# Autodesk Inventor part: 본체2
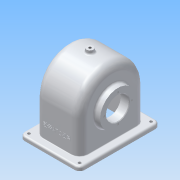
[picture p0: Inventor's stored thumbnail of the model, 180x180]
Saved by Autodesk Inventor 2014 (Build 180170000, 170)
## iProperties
Created: 2016-01
Part Number: 본체2
Material: 알루미늄 6061
Document SubType Name: Modeling
Designer: User
Mass: 794.903 g
Surface Area: 1006.9 cm^2
Volume: 293.322 cm^3
Density: 2.71 g/cm^3
Appearance: 알루미늄 - 평지
Author: User
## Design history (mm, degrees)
sketch "스케치1"
  geometry: L1 (-57, 0)-(57, 0); L2 (57, 0)-(57, -64); L3 (57, -64)-(-57, -64); L4 (-57, -64)-(-57, 0); C1 r 57 at (0, 0); 2 further points
  constraints: 8 end point, 2 coincident, 2 parallel, 1 centre point, 1 horizontal, 1 midpoint, 1 perpendicular
  dimensions: "d0" = 114 diameter of C1; "d1" = 114 distance of L2.end L3.end; "d2" = 64 distance of L1.end L2.end
extrude "돌출1" new body sketch "스케치1" stored distance "d3" = 77; taper "d4" = 0 deg
feature "쉘1" dims "d7" = 6
sketch "스케치3"
  geometry: L1 (114, 0)-(114, -77) reference; L2 (0, 0)-(114, 0) reference; L3 (0, 0)-(0, -77) reference; L4 (114, -77)-(0, -77) reference; L5 (-13, 13.5)-(127, 13.5); L6 (127, 13.5)-(127, -90.5); L7 (127, -90.5)-(-13, -90.5); L8 (-13, -90.5)-(-13, 13.5); 3 further points
  constraints: 8 end point, 2 midpoint, 2 parallel, 1 horizontal, 1 horizontal alignment, 1 perpendicular, 1 vertical alignment
  dimensions: "d8" = 140 distance of L5.start L5.end; "d9" = 104 distance of L5.end L6.end
extrude "돌출2" join sketch "스케치3" distance "d10" = 7; taper "d11" = 0 deg
fillet "모깎기1" dims "d12" = 14
node "작업 평면1"
sketch "스케치6"
  geometry: C1 r 6 at (0, 0); 1 further point
  constraints: 1 centre point, 1 coincident
  dimensions: "d36" = 12 diameter of C1
extrude "돌출4" join sketch "스케치6" stored distance "d37" = 10; taper "d38" = 0 deg
hole "구멍2" diameter "d41" = 4.459; stored, may be unused: countersink angle "d45" = 90 deg, drill point angle "d47" = 118 deg; dims "d39" = 10, "d40" = 10, "d42" = 6, "d43" = 4, "d44" = 2, "d46" = 63
fillet "모깎기4" dims "d77" = 8
sketch "스케치9"
  geometry: A1 r 8 centre (119, 82.5) between (127, 82.5) and (119, 90.5) reference; A2 r 8 centre (-5, 82.5) between (-5, 90.5) and (-13, 82.5) reference; A3 r 8 centre (-5, -5.5) between (-13, -5.5) and (-5, -13.5) reference; A4 r 8 centre (119, -5.5) between (119, -13.5) and (127, -5.5) reference; 1 further point
hole "구멍5" sketch "스케치9" at (119, 82.5), (-5, 82.5), (119, -5.5), (-5, -5.5) diameter "d78" = 5; stored, may be unused: countersink angle "d82" = 90 deg, drill point angle "d84" = 118 deg; dims "d79" = 7, "d80" = 4, "d81" = 2, "d83" = 9
fillet "모깎기5" dims "d85" = 3
sketch "스케치10"
  geometry: L1 (49, 0)-(49, -57) reference; L2 (0, 0)-(49, 0) reference; L3 (0, -57)-(0, 0) reference; L4 (-1.387, -30.398)-(50.387, -30.398); L5 (50.387, -30.398)-(50.387, -37.602); L6 (50.387, -37.602)-(-1.387, -37.602); L7 (-1.387, -37.602)-(-1.387, -30.398); L8 (0, -34)-(49, -34); L9 (-19.5, -64)-(68.5, -64) reference; L10 (24.5, 0)-(24.5, -54); L11 (-14, 0)-(-14, -57) reference; L12 (68.5, -57)-(-19.5, -57) reference; 4 further points
  constraints: 4 end point, 4 midpoint, 2 point on line, 1 horizontal alignment, 1 perpendicular, 1 vertical alignment, 2 other
  dimensions: "d86" = 30 distance between parallel lines of L9 L8; "d87" = 38.5 distance between parallel lines of L11 L10
feature "엠보싱1" sketch "스케치10" dims "d8" = 140, "d9" = 104, "d88" = 0.5, "d89" = 0
sketch "스케치11"
  geometry: L1 (-51, -64)-(-51, 0) reference; L2 (51, -64)-(-51, -64) reference; L3 (51, 0)-(51, -64) reference; C1 r 20 at (0, -4) reference; A1 r 51 centre (0, 0) between (51, 0) and (-51, 0) reference
extrude "돌출5" cut sketch "스케치11" distance "d90" = 1; taper "d91" = 0 deg
sketch "스케치12"
  geometry: L1 (-51, -64)-(-51, 0) reference; L2 (51, -64)-(-51, -64) reference; L3 (51, 0)-(51, -64) reference; C1 r 38.908 at (0, -4) reference; A1 r 51 centre (0, 0) between (51, 0) and (-51, 0) reference
extrude "돌출6" cut sketch "스케치12" distance "d92" = 1; taper "d93" = 0 deg
sketch "스케치13"
  geometry: L1 (-4, 43.197)-(-4, -48.942); L2 (-64, -33.5)-(-64, 33.5) reference; L3 (16, 35.5)-(30.899, 35.5); L4 (24, 35.5)-(24, 19.5); L5 (24, 19.5)-(16, 19.5); L6 (16, 19.5)-(16, 35.5); L7 (0, 38.5)-(43, 38.5) reference; L8 (24, 19.5)-(39.943, 38.5); L9 (30.899, 35.5)-(33.416, 38.5); L10 (-4, 33.5)-(16, 33.5); L11 (-4, 38.5)-(33.416, 38.5); L12 (-4, 38.5)-(-4, 33.5); 1 further point
  constraints: 20 end point, 6 point on line, 3 parallel, 2 perpendicular, 1 collinear, 1 horizontal, 1 vertical
  dimensions: "d95" = 60 distance between parallel lines of L1 L2; "d96" = 20 distance between parallel lines of L1 L6; "d99" = 50 deg angle of L8 L5; "d100" = 5 distance between parallel lines of L8 L9; "d102" = 5 distance between parallel lines of L10 L11; "d103" = 56 diameter of L4 L1; "d104" = 19 distance between parallel lines of L11 L5; "d105" = 3 distance between parallel lines of L11 L3
revolve "회전3" stored, may be unused: angle "d106" = 90 deg
revolve "회전4" stored, may be unused: angle "d107" = 90 deg
sketch "스케치14"
  geometry: C1 r 20 at (0, -4) reference; C2 r 31 at (0, -4)
  constraints: 1 centre point, 1 coincident
  dimensions: "d108" = 62 diameter of C2
extrude "돌출7" join sketch "스케치14" distance "d109" = 10; taper "d110" = 0 deg
hole "구멍6" diameter "d113" = 40; stored, may be unused: countersink angle "d117" = 90 deg, drill point angle "d119" = 118 deg; dims "d111" = 10, "d112" = 10, "d114" = 6, "d115" = 4, "d116" = 2, "d118" = 8
chamfer "모따기3" distance "d120" = 1; stored, may be unused: second distance "d121" = 2, angle "d122" = 45 deg
fillet "모깎기6" dims "d123" = 3
sketch "스케치15"
  geometry: C1 r 31 at (0, 0) reference; 2 further points
  constraints: 1 vertical alignment
  dimensions: "d124" = 24 distance of C1.centre point (0, 24)
hole "구멍7" sketch "스케치15" at (0, 24) diameter "d125" = 2.459; stored, may be unused: countersink angle "d129" = 90 deg, drill point angle "d131" = 118 deg; dims "d126" = 6, "d127" = 4, "d128" = 2, "d130" = 8
sketch "스케치16"
  geometry: C1 r 21 at (0, 0) reference; 2 further points
  constraints: 1 vertical alignment
  dimensions: "d135" = 28 distance of C1.centre point (0, 28)
hole "구멍8" sketch "스케치16" at (0, 28) diameter "d136" = 2.459; stored, may be unused: countersink angle "d140" = 90 deg, drill point angle "d142" = 118 deg; dims "d137" = 7, "d138" = 4, "d139" = 2, "d141" = 9
fillet "모깎기7" dims "d146" = 9
fillet "모깎기8" dims "d147" = 3
fillet "모깎기9" dims "d148" = 1
node "솔리드1"
pattern_circular "원형 패턴3" dims angle "d133" = 360 deg
pattern_circular "원형 패턴4" dims angle "d144" = 360 deg
other parameters: "d35" = 63
